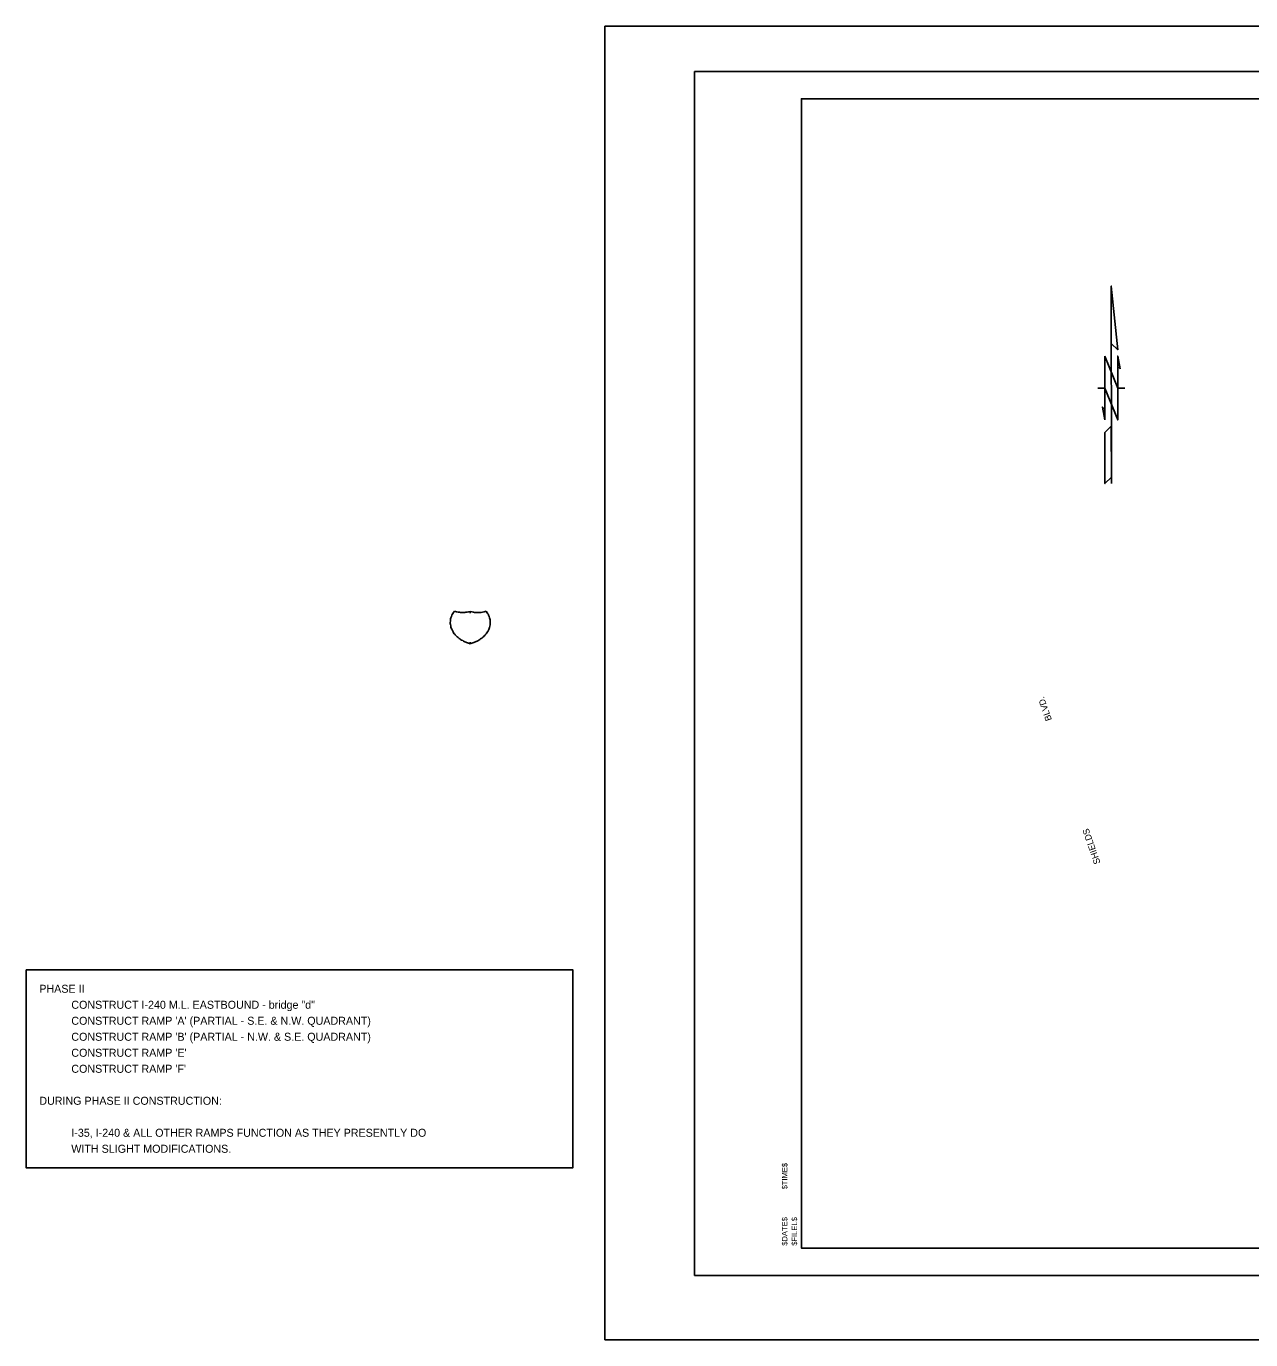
# Model space of a CAD drawing. Extents: x 2140911 to 2156666, y 139570 to 147689.
# Drawn here: x 2140911 to 2148478, y 139570 to 147689 of the extents above; entities that cross this region are included whole.
import ezdxf

# ---------------------------------------------------------------- set-up
doc = ezdxf.new("R2010")
doc.units = 0
for name, color, linetype in [('PR_Shading_Pavement_Phase_4', 7, 'Continuous'), ('SHT_North_Arrow', 7, 'Continuous'), ('SHT_Plot_Shape_Full', 7, 'Continuous'), ('SHT_Plot_Shape_Half', 7, 'Continuous'), ('SHT_Plot_Stamp', 7, 'Continuous'), ('SHT_Sheet_Border', 7, 'Continuous'), ('ST-TEXT', 7, 'Continuous')]:
    doc.layers.add(name, color=color, linetype=linetype)

msp = doc.modelspace()

# ---------------------------------------------------------------- linework, layer by layer
at = {"layer": 'PR_Shading_Pavement_Phase_4'}
for p, q in [((2143655.4, 144072), (2143655.4, 144061.5)), ((2143654.6, 143872.3), (2143654.6, 143882.8))]:
    msp.add_line(p, q, dxfattribs=at)
for points in [[(2143654.6, 143872.3), (2143639.6, 143876.8), (2143628.1, 143881.3), (2143606.3, 143891.9), (2143596.2, 143898), (2143577.7, 143911.7), (2143569.4, 143919.3), (2143555.1, 143935.6), (2143549, 143944.3), (2143539.4, 143962.7), (2143536, 143972.2), (2143531.8, 143991.8), (2143531.1, 144001.7), (2143532.7, 144021.5), (2143534.9, 144031.3), (2143541.9, 144050.3), (2143546.8, 144059.4), (2143557.1, 144074)], [(2143557.1, 144074), (2143578.1, 144067.7), (2143593.1, 144065.5), (2143623.3, 144065.2), (2143638.4, 144067.2), (2143655.4, 144072)], [(2143753.7, 144073.2), (2143763.9, 144058.6), (2143768.7, 144049.4), (2143775.6, 144030.4), (2143777.7, 144020.6), (2143779.1, 144000.7), (2143778.3, 143990.8), (2143774, 143971.3), (2143770.5, 143961.8), (2143760.8, 143943.5), (2143754.6, 143934.8), (2143740.2, 143918.6), (2143731.8, 143911.1), (2143713.2, 143897.5), (2143703, 143891.5), (2143681.2, 143881.1), (2143669.6, 143876.7), (2143654.6, 143872.3)], [(2143655.4, 144072), (2143672.3, 144067), (2143687.4, 144065), (2143717.6, 144065), (2143732.7, 144067.1), (2143753.7, 144073.2)]]:
    msp.add_open_spline(points, degree=3, dxfattribs=at)
at = {"layer": 'SHT_North_Arrow'}
for p, q in [((2147616.6, 146082.8), (2147617.1, 144862.3)), ((2147656.1, 145689.1), (2147616.6, 146082.8)), ((2147616.7, 145728.5), (2147656.1, 145689.1)), ((2147577.4, 145649.7), (2147656.2, 145452.9)), ((2147577.5, 145256), (2147577.4, 145649.7)), ((2147656.1, 145649.8), (2147671.9, 145571)), ((2147656.2, 145452.9), (2147656.1, 145649.8)), ((2147671.9, 145571), (2147656.1, 145586.8)), ((2147532.5, 145452.9), (2147577.5, 145452.9)), ((2147656.3, 145256.1), (2147577.5, 145452.9)), ((2147656.2, 145452.9), (2147656.3, 145256.1)), ((2147656.2, 145452.1), (2147701.2, 145452.1)), ((2147561.8, 145334.8), (2147577.5, 145256)), ((2147577.5, 145319), (2147561.8, 145334.8)), ((2147577.6, 145177.3), (2147616.9, 145216.7)), ((2147577.7, 144862.3), (2147577.6, 145177.3)), ((2147617.1, 144901.7), (2147577.7, 144862.3)), ((2147617.1, 144862.3), (2147617.1, 144901.7))]:
    msp.add_line(p, q, dxfattribs=at)
for points in [[(2147616.7, 145728.5), (2147656.1, 145689.1), (2147616.6, 146082.8)], [(2147577.4, 145649.7), (2147656.2, 145452.9), (2147656.3, 145256.1), (2147577.5, 145452.9)], [(2147671.9, 145571), (2147656.1, 145649.8), (2147656.1, 145586.8)], [(2147577.5, 145256), (2147577.5, 145319.1), (2147561.8, 145334.8)], [(2147616.9, 145216.7), (2147577.6, 145177.3), (2147577.7, 144862.3), (2147617.1, 144901.7)]]:
    msp.add_lwpolyline(points, close=True, dxfattribs=at)
at = {"layer": 'SHT_Plot_Shape_Full'}
msp.add_lwpolyline([(2144487.6, 147688.9), (2156666.2, 147688.9), (2156666.2, 139569.8), (2144487.6, 139569.8)], close=True, dxfattribs=at)
at = {"layer": 'SHT_Plot_Shape_Half'}
msp.add_lwpolyline([(2145041.5, 147409.9), (2156543.6, 147409.9), (2156543.6, 139967.3), (2145041.5, 139967.3)], close=True, dxfattribs=at)
at = {"layer": 'SHT_Sheet_Border'}
msp.add_lwpolyline([(2156357.5, 140136.5), (2145701.2, 140136.5), (2145701.2, 147240.7), (2156357.5, 147240.7)], close=True, dxfattribs=at)
at = {"layer": 'ST-TEXT'}
msp.add_lwpolyline([(2140911.1, 141857.2), (2144288.8, 141857.2), (2144288.8, 140632.3), (2140911.1, 140632.3)], close=True, dxfattribs=at)

# ---------------------------------------------------------------- texts
at = {"layer": 'SHT_Plot_Stamp'}
for s, p in [('$TIME$', (2145615, 140499.2)), ('$DATE$', (2145615, 140150.8)), ('$FILEL$', (2145675, 140150.8))]:
    msp.add_text(s, height=33.83, rotation=90, dxfattribs=at).set_placement(p)
at = {"layer": 'ST-TEXT'}
for s, height, rotation, p in [('BLVD.', 40, 109.06426, (2147250.1, 143402.9)), ('SHIELDS', 40, 109.06426, (2147550.3, 142517.3)), ('PHASE II', 49.45, 360, (2140991.7, 141714.6)), ('CONSTRUCT I-240 M.L. EASTBOUND - bridge "d"', 49.455, 360, (2141189.5, 141615.7)), ("CONSTRUCT RAMP 'A' (PARTIAL - S.E. & N.W. QUADRANT)", 49.455, 360, (2141189.5, 141516.8)), ("CONSTRUCT RAMP 'B' (PARTIAL - N.W. & S.E. QUADRANT)", 49.455, 360, (2141189.5, 141417.9)), ("CONSTRUCT RAMP 'E'", 49.455, 360, (2141189.5, 141319)), ("CONSTRUCT RAMP 'F'", 49.455, 360, (2141189.5, 141220)), ('DURING PHASE II CONSTRUCTION:', 49.455, 360, (2140991.7, 141022.2)), ('I-35, I-240 & ALL OTHER RAMPS FUNCTION AS THEY PRESENTLY DO', 49.455, 360, (2141189.5, 140824.4)), ('WITH SLIGHT MODIFICATIONS.', 49.455, 360, (2141189.5, 140725.5))]:
    msp.add_text(s, height=height, rotation=rotation, dxfattribs=at).set_placement(p)

doc.saveas('drawing.dxf')
